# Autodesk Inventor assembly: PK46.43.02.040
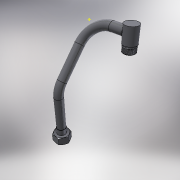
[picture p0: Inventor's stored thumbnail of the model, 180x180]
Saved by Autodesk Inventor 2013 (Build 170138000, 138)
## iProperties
Shininess: 64.0
Length Units: 11269
Angle Units: 11279
Time Units: 11290
Mass Units: 11283
Length Display Precision: 3
Angle Display Precision: 2
Compacted: True
Created: 2004-12
Part Number: PK46.43.02.040
Document SubType Name: Assembly
Designer: ELarisa
Manufacturer: Standard
Standards Organization: Custom
Density: 0.0
Volumn: 0.0
Area: 0.0
PropertySet Name: Model Information
Control State: 0
Master: False
Checked Out: False
Checked Out Date: 2008-10-09
Last Check In Date: 2008-10-09
Author: ELarisa
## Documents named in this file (5)
- C:\Product Design Suite 2013 Test Drive\Dynamic Simulation\Workspace\Assy, Chassis, Front\PK46.43.02.040.iam
- C:\Product Design Suite 2013 Test Drive\Dynamic Simulation\Workspace\Assy, Chassis, Front\PK46.43.02.017.ipt
- C:\Product Design Suite 2013 Test Drive\Dynamic Simulation\Workspace\Assy, Chassis, Front\027.07.01.019-01.ipt
- C:\Product Design Suite 2013 Test Drive\Dynamic Simulation\Workspace\Assy, Chassis, Front\027.08.00.125.ipt
- C:\Product Design Suite 2013 Test Drive\Dynamic Simulation\Workspace\Assy, Chassis, Front\PK46.43.02.019.ipt
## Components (4 placed, 4 different names)
1. PK46.43.02.017:1 — Вставка:4, Вставка:5, Угол:1
2. 027.07.01.019-01:1 — Вставка:3, Вставка:4
3. 027.08.00.125:1 — Вставка:3
4. PK46.43.02.019:1 — Вставка:5, Угол:1
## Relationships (4: Insert 3, Angle 1)
- Вставка:3 [Insert]: 027.07.01.019-01:1 ↔ 027.08.00.125:1
- Вставка:4 [Insert]: PK46.43.02.017:1 ↔ 027.07.01.019-01:1
- Вставка:5 [Insert]: PK46.43.02.017:1 ↔ PK46.43.02.019:1
- Угол:1 [Angle]: PK46.43.02.017:1 ↔ PK46.43.02.019:1
